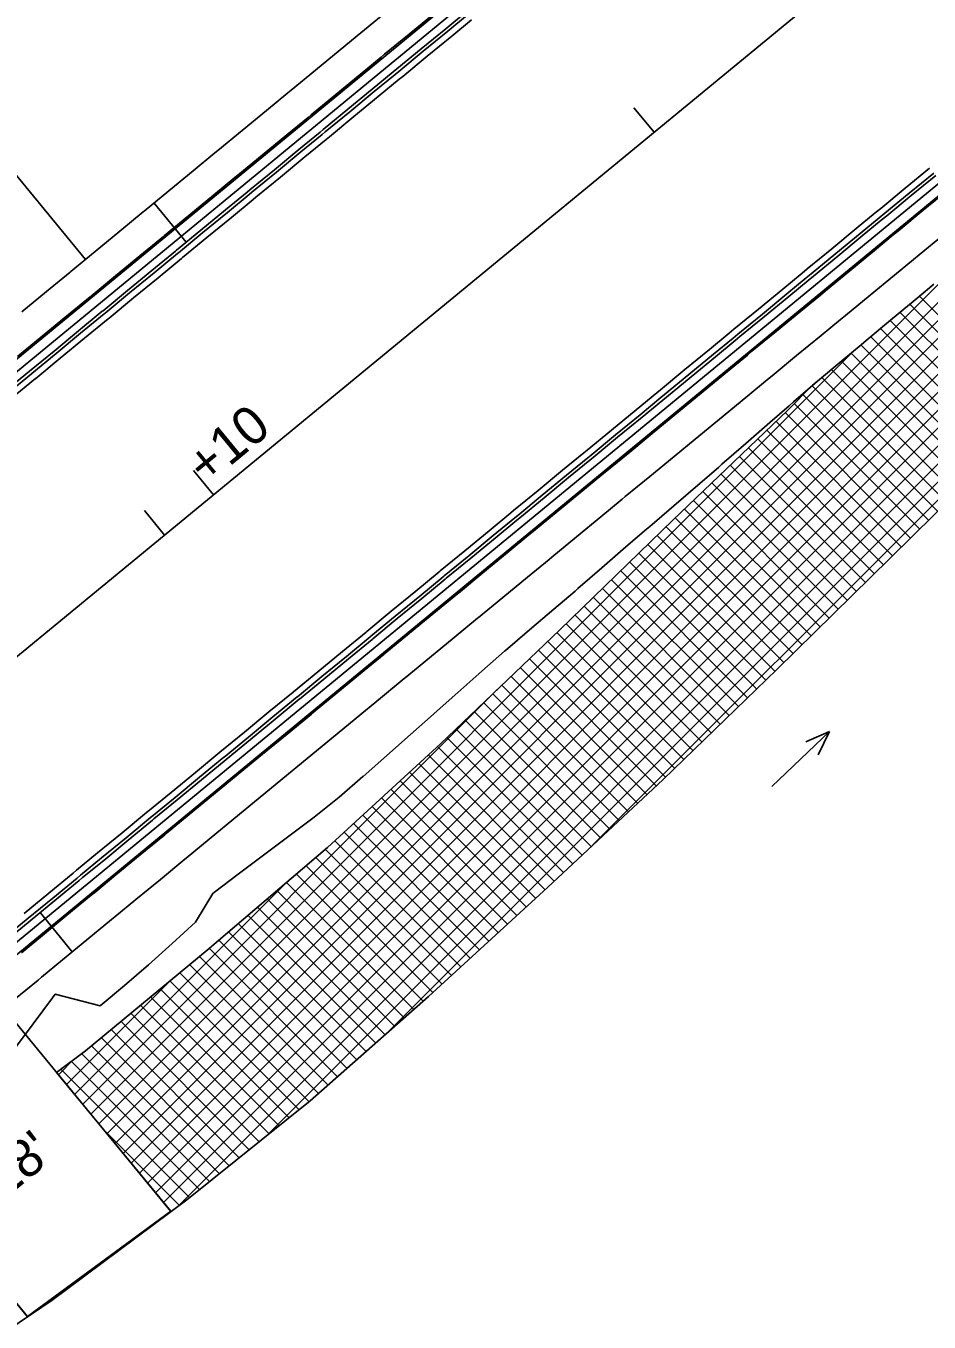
# Model space of a CAD drawing. Extents: x 1147550 to 1149124, y 2017436 to 2018779.
# Drawn here: x 1148907 to 1149049.5, y 2018399.2 to 2018603.7 of the extents above; entities that cross this region are included whole.
import ezdxf

# ---------------------------------------------------------------- set-up
doc = ezdxf.new("R2010")
doc.units = 0
for name, color, linetype in [('S_EDGE_CONCRETE', 7, 'Continuous'), ('S_HEADWALL', 7, 'Continuous'), ('S_IRON_PIN_ANNOT', 7, 'Continuous'), ('S_SECONDARY_CTL', 7, 'Continuous'), ('S_TANK', 7, 'Continuous'), ('S_TELEPHONE_UTILITIES', 7, 'Continuous'), ('S_TELEPHONE_UTILITIES_ANNOT', 7, 'Continuous')]:
    doc.layers.add(name, color=color, linetype=linetype)

msp = doc.modelspace()

# ---------------------------------------------------------------- linework, layer by layer
at = {"layer": 'S_EDGE_CONCRETE'}
msp.add_line((1148677.53, 2018316.54), (1149083.36, 2018650.43), dxfattribs=at)
for points in [[(1149002.96, 2018590.75), (1149006.14, 2018586.89)], [(1148925.74, 2018527.22), (1148928.91, 2018523.36)]]:
    msp.add_lwpolyline(points, dxfattribs=at)
at = {"layer": 'S_HEADWALL'}
for p, q in [((1148837.98, 2018662.21), (1148916.45, 2018566.84)), ((1148927.26, 2018575.74), (1148932.34, 2018569.56)), ((1148933.46, 2018533.57), (1148936.64, 2018529.71)), ((1148914.35, 2018457.64), (1148909.27, 2018463.82)), ((1148929.92, 2018416.68), (1148903.54, 2018448.74)), ((1148907.31, 2018400.08), (1148881.92, 2018430.95)), ((1148907.31, 2018400.08), (1148929.92, 2018416.68))]:
    msp.add_line(p, q, dxfattribs=at)
at = {"layer": 'S_IRON_PIN_ANNOT'}
for p, q in [((1148922.38, 2018425.84), (1149105.68, 2018609.13)), ((1148923.66, 2018424.29), (1149106.95, 2018607.58)), ((1148924.94, 2018422.74), (1149108.23, 2018606.03)), ((1148926.21, 2018421.18), (1149109.51, 2018604.48)), ((1148927.49, 2018419.63), (1149110.78, 2018602.93)), ((1148928.77, 2018418.08), (1149112.06, 2018601.38)), ((1148931, 2018417.49), (1149113.34, 2018599.82)), ((1148944.72, 2018428.38), (1149114.61, 2018598.27)), ((1148921.11, 2018427.39), (1149089.87, 2018596.15)), ((1148963.77, 2018444.6), (1149115.89, 2018596.72)), ((1148996.51, 2018474.51), (1149117.17, 2018595.17)), ((1148919.83, 2018428.94), (1149072.62, 2018581.74)), ((1148918.55, 2018430.5), (1149054.51, 2018566.45)), ((1149046.51, 2018559.78), (1149065.09, 2018541.2)), ((1149048.05, 2018561.06), (1149066.49, 2018542.62)), ((1149043.41, 2018557.22), (1149062.29, 2018538.34)), ((1149044.96, 2018558.5), (1149063.69, 2018539.77)), ((1149041.87, 2018555.93), (1149060.88, 2018536.92)), ((1149038.78, 2018553.36), (1149058.03, 2018534.11)), ((1149040.33, 2018554.65), (1149059.45, 2018535.52)), ((1148917.28, 2018432.05), (1149037.65, 2018552.42)), ((1149037.24, 2018552.08), (1149056.61, 2018532.71)), ((1149034.15, 2018549.51), (1149053.76, 2018529.9)), ((1149035.7, 2018550.79), (1149055.18, 2018531.31)), ((1149031.07, 2018546.93), (1149050.91, 2018527.1)), ((1149032.61, 2018548.22), (1149052.33, 2018528.5)), ((1149029.66, 2018545.51), (1149049.48, 2018525.69)), ((1149028.25, 2018544.1), (1149048.06, 2018524.29)), ((1149025.39, 2018541.3), (1149045.21, 2018521.48)), ((1149026.83, 2018542.69), (1149046.63, 2018522.88)), ((1149023.94, 2018539.92), (1149043.79, 2018520.08)), ((1149021.05, 2018537.15), (1149040.93, 2018517.28)), ((1149022.5, 2018538.53), (1149042.36, 2018518.67)), ((1149019.61, 2018535.76), (1149039.5, 2018515.88)), ((1149016.72, 2018532.99), (1149036.64, 2018513.08)), ((1149018.17, 2018534.38), (1149038.07, 2018514.48)), ((1149015.28, 2018531.61), (1149035.21, 2018511.68)), ((1149012.39, 2018528.84), (1149032.35, 2018508.88)), ((1149013.84, 2018530.23), (1149033.78, 2018510.28)), ((1149010.95, 2018527.46), (1149030.92, 2018507.48)), ((1149008.07, 2018524.68), (1149028.07, 2018504.68)), ((1149009.5, 2018526.07), (1149029.5, 2018506.08)), ((1149006.63, 2018523.29), (1149026.64, 2018503.28)), ((1149003.76, 2018520.51), (1149023.77, 2018500.5)), ((1149005.19, 2018521.9), (1149025.21, 2018501.89)), ((1149002.32, 2018519.11), (1149022.33, 2018499.11)), ((1148999.45, 2018516.33), (1149019.45, 2018496.33)), ((1149000.88, 2018517.72), (1149020.89, 2018497.72)), ((1148998.01, 2018514.94), (1149018.01, 2018494.94)), ((1148995.14, 2018512.15), (1149015.14, 2018492.16)), ((1148996.57, 2018513.55), (1149016.57, 2018493.55)), ((1148993.7, 2018510.76), (1149013.7, 2018490.77)), ((1148992.26, 2018509.37), (1149012.26, 2018489.38)), ((1148989.38, 2018506.6), (1149009.38, 2018486.6)), ((1148990.82, 2018507.98), (1149010.82, 2018487.99)), ((1148987.93, 2018505.22), (1149007.94, 2018485.21)), ((1148985.03, 2018502.46), (1149005.03, 2018482.47)), ((1148986.48, 2018503.84), (1149006.49, 2018483.83)), ((1148983.58, 2018501.08), (1149003.56, 2018481.1)), ((1148916, 2018433.6), (1148981.45, 2018499.05)), ((1148980.69, 2018498.32), (1149000.64, 2018478.37)), ((1148982.13, 2018499.7), (1149002.1, 2018479.73)), ((1148979.24, 2018496.94), (1148999.18, 2018477)), ((1148976.34, 2018494.18), (1148996.25, 2018474.27)), ((1148977.79, 2018495.56), (1148997.71, 2018475.64)), ((1148974.89, 2018492.8), (1148994.79, 2018472.9)), ((1148971.99, 2018490.05), (1148991.86, 2018470.17)), ((1148973.44, 2018491.42), (1148993.33, 2018471.54)), ((1148970.51, 2018488.69), (1148990.4, 2018468.81)), ((1148967.57, 2018485.99), (1148987.46, 2018466.09)), ((1148969.04, 2018487.34), (1148988.94, 2018467.44)), ((1148966.09, 2018484.63), (1148985.99, 2018464.74)), ((1148963.14, 2018481.92), (1148983.03, 2018462.03)), ((1148964.62, 2018483.28), (1148984.51, 2018463.38)), ((1148961.67, 2018480.57), (1148981.56, 2018460.68)), ((1148958.72, 2018477.86), (1148978.61, 2018457.97)), ((1148960.2, 2018479.21), (1148980.08, 2018459.33)), ((1148957.25, 2018476.5), (1148977.13, 2018456.62)), ((1148954.29, 2018473.8), (1148974.18, 2018453.92)), ((1148955.78, 2018475.15), (1148975.66, 2018455.27)), ((1148952.76, 2018472.5), (1148972.71, 2018452.56)), ((1148949.71, 2018469.9), (1148969.74, 2018449.87)), ((1148951.24, 2018471.2), (1148971.23, 2018451.21)), ((1148914.72, 2018435.15), (1148948.14, 2018468.57)), ((1148946.65, 2018467.3), (1148966.74, 2018447.22)), ((1148948.18, 2018468.6), (1148968.24, 2018448.55)), ((1148945.12, 2018466), (1148965.23, 2018445.89)), ((1148942.07, 2018463.4), (1148962.23, 2018443.24)), ((1148943.6, 2018464.7), (1148963.73, 2018444.57)), ((1148940.54, 2018462.1), (1148960.73, 2018441.91)), ((1148937.49, 2018459.5), (1148957.72, 2018439.26)), ((1148939.01, 2018460.8), (1148959.23, 2018440.59)), ((1148935.96, 2018458.2), (1148956.22, 2018437.93)), ((1148932.86, 2018455.63), (1148953.22, 2018435.28)), ((1148934.41, 2018456.91), (1148954.72, 2018436.61)), ((1148913.45, 2018436.7), (1148930.07, 2018453.32)), ((1148929.77, 2018453.08), (1148950.13, 2018432.71)), ((1148931.32, 2018454.35), (1148951.71, 2018433.96)), ((1148928.22, 2018451.8), (1148948.56, 2018431.45)), ((1148925.12, 2018449.24), (1148945.42, 2018428.94)), ((1148926.67, 2018450.52), (1148946.99, 2018430.19)), ((1148923.57, 2018447.96), (1148943.85, 2018427.68)), ((1148920.47, 2018445.4), (1148940.7, 2018425.17)), ((1148922.02, 2018446.68), (1148942.27, 2018426.42)), ((1148917.37, 2018442.84), (1148937.56, 2018422.65)), ((1148918.92, 2018444.12), (1148939.13, 2018423.91)), ((1148912.17, 2018438.25), (1148914.62, 2018440.71)), ((1148915.8, 2018441.59), (1148935.99, 2018421.4)), ((1148912.56, 2018439.16), (1148932.84, 2018418.88)), ((1148914.18, 2018440.38), (1148934.42, 2018420.14)), ((1148919.24, 2018429.66), (1148931.24, 2018417.66)), ((1148929.58, 2018416.49), (1148929.62, 2018416.45)), ((1148926.31, 2018414.1), (1148926.38, 2018414.04)), ((1148927.95, 2018415.3), (1148928, 2018415.25)), ((1148924.68, 2018412.9), (1148924.76, 2018412.83)), ((1148921.42, 2018410.51), (1148921.52, 2018410.41)), ((1148923.05, 2018411.71), (1148923.14, 2018411.62)), ((1148918.16, 2018408.11), (1148918.28, 2018407.99)), ((1148919.79, 2018409.31), (1148919.9, 2018409.2)), ((1148919.85, 2018409.16), (1148920.56, 2018409.88)), ((1148916.53, 2018406.92), (1148916.66, 2018406.78)), ((1148913.27, 2018404.52), (1148913.42, 2018404.37)), ((1148914.9, 2018405.72), (1148915.04, 2018405.57)), ((1148909.24, 2018401.38), (1148909.92, 2018402.07)), ((1148910, 2018402.13), (1148910.14, 2018401.99)), ((1148911.63, 2018403.32), (1148911.8, 2018403.16)), ((1148908.37, 2018400.93), (1148908.45, 2018400.85))]:
    msp.add_line(p, q, dxfattribs=at)
for points in [[(1148725.05, 2018295.78), (1148737.29, 2018302.31), (1148759.39, 2018313.93), (1148781.46, 2018325.68), (1148803.37, 2018337.66), (1148825.28, 2018349.66), (1148846.98, 2018361.91), (1148869.23, 2018375.5), (1148890.45, 2018388.71), (1148911.17, 2018402.69), (1148932.43, 2018418.55), (1148951.91, 2018434.12), (1148970.58, 2018450.61), (1148989.32, 2018467.79), (1149007.56, 2018484.84), (1149025.52, 2018502.19), (1149043.36, 2018519.65), (1149061.14, 2018537.18), (1149078.8, 2018555.13), (1149096.46, 2018572.78), (1149114.15, 2018590.39), (1149117.96, 2018594.21)], [(1149050.3, 2018562.92), (1149047.32, 2018560.45), (1149043.47, 2018557.26), (1149039.62, 2018554.06), (1149038.82, 2018553.4), (1149035.78, 2018550.86), (1149031.94, 2018547.66), (1149031.17, 2018547.02)], [(1149031.17, 2018547.02), (1149027.18, 2018543.02), (1149009.16, 2018525.75), (1148991.23, 2018508.37), (1148972.44, 2018490.46), (1148954.61, 2018474.07), (1148935.64, 2018457.92), (1148916.42, 2018442.05), (1148911.86, 2018438.63), (1148929.89, 2018416.72), (1148907.28, 2018400.13), (1148889.2, 2018422.11), (1148877.8, 2018414.13), (1148857.12, 2018400.11), (1148842.25, 2018391.1)]]:
    msp.add_lwpolyline(points, dxfattribs=at)
at = {"layer": 'S_SECONDARY_CTL'}
msp.add_lwpolyline([(1148905.09, 2018442.14), (1148908.17, 2018446.27), (1148911.24, 2018450.4), (1148911.67, 2018450.99), (1148918.75, 2018449.14), (1148922.6, 2018452.34), (1148926.4, 2018455.59), (1148926.92, 2018456.04), (1148930.12, 2018458.93), (1148933.8, 2018462.33), (1148936.55, 2018466.86), (1148936.77, 2018467.03), (1148940.55, 2018469.87), (1148944.54, 2018472.88), (1148948.54, 2018475.89), (1148948.54, 2018475.89), (1148952.54, 2018478.9), (1148956.45, 2018482.02), (1148960.2, 2018485.27), (1148960.23, 2018485.29), (1148963.97, 2018488.61), (1148967.72, 2018491.93), (1148971.35, 2018495.14), (1148971.47, 2018495.25), (1148975.21, 2018498.56), (1148978.96, 2018501.88), (1148982.56, 2018505.04), (1148982.72, 2018505.18), (1148986.51, 2018508.44), (1148990.32, 2018511.68), (1148993.68, 2018514.54), (1148994.13, 2018514.92), (1148997.9, 2018518.2), (1149001.68, 2018521.49), (1149004.97, 2018524.31), (1149005.47, 2018524.74), (1149009.27, 2018527.99), (1149013.06, 2018531.25), (1149016.29, 2018534.05), (1149016.84, 2018534.53), (1149020.61, 2018537.82), (1149024.39, 2018541.1), (1149027.45, 2018543.75), (1149028.16, 2018544.38), (1149031.94, 2018547.66), (1149035.78, 2018550.86), (1149038.82, 2018553.4), (1149039.62, 2018554.06), (1149043.47, 2018557.26), (1149047.32, 2018560.45), (1149050.3, 2018562.92)], dxfattribs=at)
at = {"layer": 'S_TANK'}
for p, q in [((1149024.74, 2018483.72), (1149033.84, 2018492.39)), ((1149033.84, 2018492.39), (1149030.09, 2018490.75)), ((1149033.84, 2018492.39), (1149032.02, 2018488.73))]:
    msp.add_line(p, q, dxfattribs=at)
at = {"layer": 'S_TELEPHONE_UTILITIES'}
for points in [[(1148906.41, 2018558.58), (1148910.27, 2018561.76), (1148914.01, 2018564.83), (1148914.13, 2018564.94), (1148917.99, 2018568.11), (1148921.85, 2018571.29), (1148925.56, 2018574.34), (1148925.71, 2018574.47), (1148929.57, 2018577.64), (1148933.44, 2018580.82), (1148936.85, 2018583.63), (1148937.3, 2018584), (1148941.16, 2018587.17), (1148945.02, 2018590.35), (1148948.37, 2018593.11), (1148948.88, 2018593.53), (1148952.74, 2018596.7), (1148956.6, 2018599.88), (1148959.9, 2018602.59), (1148960.46, 2018603.06), (1148964.32, 2018606.23)], [(1148903.77, 2018546.05), (1148907.6, 2018549.21), (1148907.63, 2018549.23), (1148911.49, 2018552.4), (1148915.35, 2018555.58), (1148919.09, 2018558.66), (1148919.21, 2018558.76), (1148923.07, 2018561.93), (1148926.93, 2018565.11), (1148930.64, 2018568.16), (1148930.8, 2018568.29), (1148934.66, 2018571.46), (1148938.52, 2018574.64), (1148941.93, 2018577.45), (1148942.38, 2018577.82), (1148946.24, 2018580.99), (1148950.1, 2018584.17), (1148953.45, 2018586.93), (1148953.96, 2018587.35), (1148957.82, 2018590.52), (1148961.69, 2018593.7), (1148964.98, 2018596.41), (1148965.55, 2018596.88), (1148969.41, 2018600.06), (1148973.27, 2018603.23), (1148976.39, 2018605.8)], [(1148904.09, 2018545.66), (1148907.92, 2018548.82), (1148907.95, 2018548.84), (1148911.81, 2018552.02), (1148915.67, 2018555.2), (1148919.41, 2018558.27), (1148919.53, 2018558.37), (1148923.39, 2018561.55), (1148927.25, 2018564.73), (1148930.96, 2018567.77), (1148931.11, 2018567.9), (1148934.97, 2018571.08), (1148938.84, 2018574.26), (1148942.25, 2018577.06), (1148942.7, 2018577.43), (1148946.56, 2018580.61), (1148950.42, 2018583.79), (1148953.77, 2018586.54), (1148954.28, 2018586.96), (1148958.14, 2018590.14), (1148962, 2018593.32), (1148965.3, 2018596.03), (1148965.86, 2018596.49), (1148969.73, 2018599.67), (1148973.59, 2018602.85), (1148976.71, 2018605.42)], [(1148904.72, 2018544.89), (1148908.55, 2018548.05), (1148908.58, 2018548.07), (1148912.44, 2018551.25), (1148916.3, 2018554.42), (1148920.04, 2018557.5), (1148920.17, 2018557.6), (1148924.03, 2018560.78), (1148927.89, 2018563.95), (1148931.59, 2018567), (1148931.75, 2018567.13), (1148935.61, 2018570.31), (1148939.47, 2018573.48), (1148942.88, 2018576.29), (1148943.33, 2018576.66), (1148947.19, 2018579.84), (1148951.05, 2018583.01), (1148954.4, 2018585.77), (1148954.92, 2018586.19), (1148958.78, 2018589.37), (1148962.64, 2018592.54), (1148965.93, 2018595.26), (1148966.5, 2018595.72), (1148970.36, 2018598.9), (1148974.22, 2018602.07), (1148977.35, 2018604.65)], [(1148905.72, 2018551.54), (1148909.58, 2018554.72), (1148913.45, 2018557.9), (1148917.18, 2018560.97), (1148917.31, 2018561.07), (1148921.17, 2018564.25), (1148925.03, 2018567.43), (1148928.73, 2018570.47), (1148928.89, 2018570.6), (1148932.75, 2018573.78), (1148936.61, 2018576.96), (1148940.02, 2018579.76), (1148940.47, 2018580.13), (1148944.33, 2018583.31), (1148948.2, 2018586.49), (1148951.55, 2018589.24), (1148952.06, 2018589.66), (1148955.92, 2018592.84), (1148959.78, 2018596.02), (1148963.08, 2018598.73), (1148963.64, 2018599.2), (1148967.5, 2018602.37), (1148971.36, 2018605.55)], [(1148904.09, 2018460.2), (1148907.41, 2018462.93), (1148911.27, 2018466.11), (1148915.13, 2018469.28), (1148915.66, 2018469.72), (1148918.99, 2018472.46), (1148922.85, 2018475.64), (1148926.71, 2018478.81), (1148926.93, 2018478.99), (1148930.57, 2018481.99), (1148934.43, 2018485.17), (1148938.29, 2018488.34), (1148938.3, 2018488.34), (1148942.16, 2018491.52), (1148946.02, 2018494.7), (1148949.85, 2018497.85), (1148949.88, 2018497.87), (1148953.74, 2018501.05), (1148957.6, 2018504.23), (1148961.34, 2018507.3), (1148961.46, 2018507.4), (1148965.32, 2018510.58), (1148969.18, 2018513.76), (1148972.89, 2018516.8), (1148973.05, 2018516.93), (1148976.91, 2018520.11), (1148980.77, 2018523.29), (1148984.18, 2018526.09), (1148984.63, 2018526.46), (1148988.49, 2018529.64), (1148992.35, 2018532.82), (1148995.7, 2018535.57), (1148996.21, 2018535.99), (1149000.07, 2018539.17), (1149003.94, 2018542.35), (1149007.23, 2018545.06), (1149007.8, 2018545.53), (1149011.66, 2018548.7), (1149015.52, 2018551.88), (1149018.64, 2018554.45), (1149019.38, 2018555.06), (1149023.24, 2018558.23), (1149027.1, 2018561.41), (1149030.16, 2018563.93), (1149030.96, 2018564.59), (1149034.82, 2018567.76), (1149038.69, 2018570.94), (1149041.68, 2018573.4), (1149042.55, 2018574.12), (1149046.41, 2018577.29), (1149050.27, 2018580.47)], [(1148904.41, 2018459.82), (1148907.72, 2018462.54), (1148911.59, 2018465.72), (1148915.45, 2018468.9), (1148915.98, 2018469.34), (1148919.31, 2018472.07), (1148923.17, 2018475.25), (1148927.03, 2018478.43), (1148927.24, 2018478.6), (1148930.89, 2018481.6), (1148934.75, 2018484.78), (1148938.61, 2018487.96), (1148938.61, 2018487.96), (1148942.47, 2018491.13), (1148946.34, 2018494.31), (1148950.17, 2018497.47), (1148950.2, 2018497.49), (1148954.06, 2018500.66), (1148957.92, 2018503.84), (1148961.66, 2018506.92), (1148961.78, 2018507.02), (1148965.64, 2018510.2), (1148969.5, 2018513.37), (1148973.21, 2018516.42), (1148973.36, 2018516.55), (1148977.22, 2018519.73), (1148981.09, 2018522.9), (1148984.5, 2018525.71), (1148984.95, 2018526.08), (1148988.81, 2018529.26), (1148992.67, 2018532.43), (1148996.02, 2018535.19), (1148996.53, 2018535.61), (1149000.39, 2018538.79), (1149004.25, 2018541.96), (1149007.55, 2018544.67), (1149008.11, 2018545.14), (1149011.98, 2018548.32), (1149015.84, 2018551.49), (1149018.96, 2018554.06), (1149019.7, 2018554.67), (1149023.56, 2018557.85), (1149027.42, 2018561.02), (1149030.48, 2018563.54), (1149031.28, 2018564.2), (1149035.14, 2018567.38), (1149039, 2018570.55), (1149041.99, 2018573.01), (1149042.86, 2018573.73), (1149046.73, 2018576.91), (1149050.59, 2018580.08)], [(1148906.77, 2018463.7), (1148910.63, 2018466.88), (1148914.49, 2018470.06), (1148915.03, 2018470.5), (1148918.35, 2018473.23), (1148922.22, 2018476.41), (1148926.08, 2018479.59), (1148926.29, 2018479.76), (1148929.94, 2018482.76), (1148933.8, 2018485.94), (1148937.66, 2018489.11), (1148937.66, 2018489.12), (1148941.52, 2018492.29), (1148945.38, 2018495.47), (1148949.22, 2018498.62), (1148949.24, 2018498.65), (1148953.1, 2018501.82), (1148956.97, 2018505), (1148960.7, 2018508.08), (1148960.83, 2018508.18), (1148964.69, 2018511.35), (1148968.55, 2018514.53), (1148972.25, 2018517.58), (1148972.41, 2018517.71), (1148976.27, 2018520.88), (1148980.13, 2018524.06), (1148983.54, 2018526.87), (1148983.99, 2018527.24), (1148987.86, 2018530.41), (1148991.72, 2018533.59), (1148995.07, 2018536.35), (1148995.58, 2018536.77), (1148999.44, 2018539.94), (1149003.3, 2018543.12), (1149006.6, 2018545.83), (1149007.16, 2018546.3), (1149011.02, 2018549.47), (1149014.88, 2018552.65), (1149018.01, 2018555.22), (1149018.74, 2018555.83), (1149022.61, 2018559), (1149026.47, 2018562.18), (1149029.53, 2018564.7), (1149030.33, 2018565.36), (1149034.19, 2018568.53), (1149038.05, 2018571.71), (1149041.04, 2018574.17), (1149041.91, 2018574.89), (1149045.77, 2018578.06), (1149049.63, 2018581.24)], [(1148906.32, 2018457.5), (1148909.63, 2018460.23), (1148913.49, 2018463.4), (1148917.35, 2018466.58), (1148917.89, 2018467.02), (1148921.21, 2018469.76), (1148925.07, 2018472.93), (1148928.94, 2018476.11), (1148929.15, 2018476.29), (1148932.8, 2018479.29), (1148936.66, 2018482.46), (1148940.52, 2018485.64), (1148940.52, 2018485.64), (1148944.38, 2018488.82), (1148948.24, 2018491.99), (1148952.08, 2018495.15), (1148952.1, 2018495.17), (1148955.96, 2018498.35), (1148959.83, 2018501.52), (1148963.56, 2018504.6), (1148963.69, 2018504.7), (1148967.55, 2018507.88), (1148971.41, 2018511.06), (1148975.11, 2018514.1), (1148975.27, 2018514.23), (1148979.13, 2018517.41), (1148982.99, 2018520.59), (1148986.4, 2018523.39), (1148986.85, 2018523.76), (1148990.71, 2018526.94), (1148994.58, 2018530.12), (1148997.93, 2018532.87), (1148998.44, 2018533.29), (1149002.3, 2018536.47), (1149006.16, 2018539.65), (1149009.45, 2018542.36), (1149010.02, 2018542.82), (1149013.88, 2018546), (1149017.74, 2018549.18), (1149020.87, 2018551.75), (1149021.6, 2018552.35), (1149025.46, 2018555.53), (1149029.33, 2018558.71), (1149032.39, 2018561.22), (1149033.19, 2018561.88), (1149037.05, 2018565.06), (1149040.91, 2018568.24), (1149043.9, 2018570.7), (1149044.77, 2018571.41), (1149048.63, 2018574.59), (1149052.49, 2018577.77)], [(1148905.08, 2018450.01), (1148908.95, 2018453.19), (1148909.49, 2018453.64), (1148912.81, 2018456.37), (1148916.67, 2018459.54), (1148920.53, 2018462.72), (1148921.06, 2018463.16), (1148924.39, 2018465.9), (1148928.25, 2018469.07), (1148932.11, 2018472.25), (1148932.33, 2018472.43), (1148935.97, 2018475.43), (1148939.83, 2018478.6), (1148943.69, 2018481.78), (1148943.7, 2018481.78), (1148947.56, 2018484.96), (1148951.42, 2018488.13), (1148955.25, 2018491.29), (1148955.28, 2018491.31), (1148959.14, 2018494.49), (1148963, 2018497.66), (1148966.74, 2018500.74), (1148966.86, 2018500.84), (1148970.72, 2018504.02), (1148974.59, 2018507.19), (1148978.29, 2018510.24), (1148978.45, 2018510.37), (1148982.31, 2018513.55), (1148986.17, 2018516.72), (1148989.58, 2018519.53), (1148990.03, 2018519.9), (1148993.89, 2018523.08), (1148997.75, 2018526.25), (1149001.1, 2018529.01), (1149001.61, 2018529.43), (1149005.47, 2018532.61), (1149009.34, 2018535.78), (1149012.63, 2018538.5), (1149013.2, 2018538.96), (1149017.06, 2018542.14), (1149020.92, 2018545.31), (1149024.05, 2018547.89), (1149024.78, 2018548.49), (1149028.64, 2018551.67), (1149032.5, 2018554.84), (1149035.56, 2018557.36), (1149036.36, 2018558.02), (1149040.22, 2018561.2), (1149044.09, 2018564.37), (1149047.08, 2018566.84), (1149047.95, 2018567.55), (1149051.81, 2018570.73)]]:
    msp.add_lwpolyline(points, dxfattribs=at)
at = {"layer": 'S_TELEPHONE_UTILITIES_ANNOT'}
for p, q in [((1148876.42, 2018527.12), (1149060.33, 2018678.42)), ((1148876.42, 2018527.12), (1149060.33, 2018678.42)), ((1148877.38, 2018525.96), (1149061.28, 2018677.26)), ((1148877.38, 2018525.96), (1149061.28, 2018677.26)), ((1148863.62, 2018424.64), (1149080.84, 2018603.35)), ((1148863.62, 2018424.64), (1149080.84, 2018603.35)), ((1148864.57, 2018423.48), (1149081.79, 2018602.19)), ((1148864.57, 2018423.48), (1149081.79, 2018602.19))]:
    msp.add_line(p, q, dxfattribs=at)

# ---------------------------------------------------------------- texts
at = {"layer": 'S_HEADWALL'}
for s, p in [('+10', (1148935.49, 2018531.1)), ("28'", (1148903.64, 2018418.57))]:
    msp.add_text(s, height=6, rotation=39.4453, dxfattribs=at).set_placement(p)

doc.saveas('drawing.dxf')
